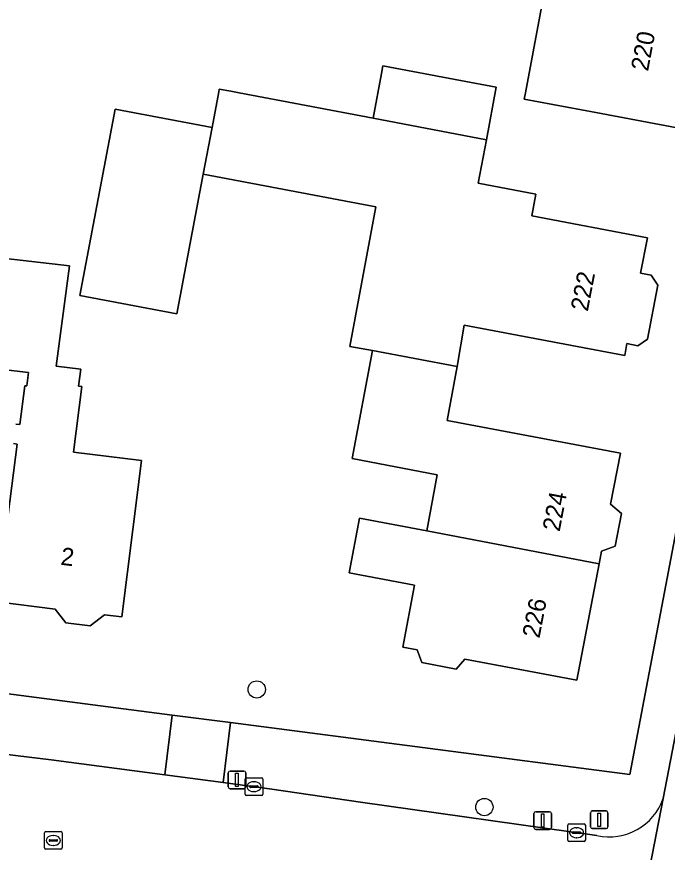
# Model space of a CAD drawing. Extents: x 161258 to 161838, y 380833 to 381727.
# Drawn here: x 161737.48 to 161774.37, y 381335.28 to 381382.67 of the extents above; entities that cross this region are included whole.
import ezdxf

# ---------------------------------------------------------------- set-up
doc = ezdxf.new("R2010")
doc.units = 0
for name, color, linetype in [('IMGEO_Boom', 7, 'Continuous'), ('IMGEO_Erf', 7, 'Continuous'), ('IMGEO_Fietspad_gesloten', 7, 'Continuous'), ('IMGEO_Kolk', 7, 'Continuous'), ('IMGEO_Lichtmast', 7, 'Continuous'), ('IMGEO_Pand', 7, 'Continuous'), ('IMGEO_Pand_nummerreeks', 7, 'Continuous'), ('IMGEO_Rijbaan_lokaal_open', 7, 'Continuous'), ('IMGEO_Rioolput', 7, 'Continuous'), ('IMGEO_Verkeersregelinstallatiepaal', 7, 'Continuous'), ('IMGEO_Voetpad_open', 7, 'Continuous')]:
    doc.layers.add(name, color=color, linetype=linetype)

msp = doc.modelspace()

# ---------------------------------------------------------------- linework, layer by layer
at = {"layer": 'IMGEO_Boom'}
for centre in [(161751.09, 381344.514), (161764, 381337.844)]:
    msp.add_circle(centre, 0.489, dxfattribs=at)
at = {"layer": 'IMGEO_Erf'}
for points in [[(161712.163, 381347.496), (161746.295, 381343.062), (161749.605, 381342.632), (161772.254, 381339.69), (161786.798, 381416.269), (161787.036, 381416.236), (161788.344, 381422.794), (161783.743, 381423.687), (161780.505, 381424.315), (161777.422, 381424.913), (161778.75, 381431.76), (161775.848, 381432.311), (161776.306, 381434.768), (161782.251, 381433.662), (161783.039, 381437.877), (161784.344, 381444.861), (161780.238, 381445.628), (161780.029, 381444.508), (161772.824, 381445.856)], [(161735.68, 381369.079), (161740.464, 381368.537), (161739.721, 381362.851), (161741.107, 381362.678), (161740.985, 381361.71), (161741.162, 381361.688), (161740.696, 381357.98), (161744.554, 381357.496), (161744.065, 381353.595), (161743.442, 381348.633), (161742.465, 381348.756), (161741.649, 381348.122), (161740.257, 381348.296), (161739.661, 381349.064), (161736.377, 381349.475)], [(161737.432, 381359.565), (161737.662, 381359.537), (161737.938, 381361.743), (161738.052, 381361.73), (161738.149, 381362.494), (161735.049, 381362.846)], [(161737, 381354.437), (161737.501, 381358.434), (161737.293, 381358.46)]]:
    msp.add_lwpolyline(points, dxfattribs=at)
for points in [[(161772.844, 381389.277), (161772.118, 381385.422), (161776.791, 381384.539), (161775.234, 381376.303), (161770.322, 381377.232), (161766.263, 381377.999), (161766.33, 381378.356), (161767.586, 381385.049), (161767.219, 381385.119), (161765.849, 381385.38), (161763.911, 381385.748), (161763.533, 381385.82), (161763.122, 381385.898), (161764.068, 381390.901), (161758.838, 381391.869), (161759.471, 381395.29), (161765.709, 381394.135), (161765.076, 381390.715), (161766.095, 381390.526)], [(161757.685, 381376.912), (161758.164, 381379.441), (161758.247, 381379.879), (161762.644, 381379.05), (161764.673, 381378.668), (161764.111, 381375.692), (161763.646, 381373.225), (161766.918, 381372.607), (161766.684, 381371.367), (161773.243, 381370.131), (161772.855, 381368.115), (161773.458, 381368.002), (161773.832, 381367.453), (161773.254, 381364.387), (161772.706, 381364.012), (161772.086, 381364.128), (161771.956, 381363.458), (161762.847, 381365.174), (161762.463, 381362.825), (161761.888, 381359.773), (161771.713, 381357.922), (161771.157, 381355.03), (161771.772, 381354.502), (161771.42, 381352.634), (161770.644, 381352.361), (161770.505, 381351.637), (161769.237, 381345.041), (161762.882, 381346.239), (161762.394, 381345.671), (161760.449, 381346.038), (161760.196, 381346.759), (161759.381, 381346.913), (161760.044, 381350.429), (161756.34, 381351.127), (161756.923, 381354.222), (161760.728, 381353.505), (161761.329, 381356.694), (161756.496, 381357.605), (161757.651, 381363.731), (161756.374, 381363.971), (161757.841, 381371.885), (161748.057, 381373.742), (161746.562, 381365.815), (161741.062, 381366.849), (161743.058, 381377.43), (161748.556, 381376.386), (161748.939, 381378.417), (161748.967, 381378.567), (161749.615, 381378.444), (161750.102, 381378.351)]]:
    msp.add_lwpolyline(points, close=True, dxfattribs=at)
at = {"layer": 'IMGEO_Fietspad_gesloten'}
msp.add_lwpolyline([(161776.826, 381341.153), (161777.049, 381342.372), (161777.831, 381346.224), (161778.926, 381351.995), (161776.847, 381352.346), (161774.147, 381338.339), (161771.375, 381324.109), (161770.217, 381317.745), (161772.289, 381317.394), (161772.887, 381320.696), (161773.43, 381323.525)], close=True, dxfattribs=at)
at = {"layer": 'IMGEO_Kolk'}
for p, q in [((161750.43, 381338.576), (161750.43, 381339.428)), ((161750.505, 381339.502), (161751.357, 381339.502)), ((161751.431, 381339.428), (161751.431, 381338.576)), ((161750.689, 381338.996), (161750.689, 381339.008)), ((161751.127, 381338.959), (161750.729, 381338.959)), ((161750.732, 381339.045), (161751.13, 381339.045)), ((161750.918, 381339.282), (161750.943, 381339.282)), ((161751.173, 381339.008), (161751.173, 381338.996)), ((161751.357, 381338.502), (161750.505, 381338.502)), ((161750.941, 381338.722), (161750.916, 381338.722)), ((161768.726, 381335.963), (161768.726, 381336.815)), ((161768.801, 381336.889), (161769.653, 381336.889)), ((161769.214, 381336.669), (161769.239, 381336.669)), ((161769.727, 381336.815), (161769.727, 381335.963)), ((161768.985, 381336.383), (161768.985, 381336.395)), ((161769.423, 381336.346), (161769.025, 381336.346)), ((161769.028, 381336.432), (161769.426, 381336.432)), ((161769.237, 381336.109), (161769.212, 381336.109)), ((161769.469, 381336.395), (161769.469, 381336.383)), ((161769.653, 381335.889), (161768.801, 381335.889))]:
    msp.add_line(p, q, dxfattribs=at)
for points in [[(161750.43, 381338.576), (161750.43, 381339.428)], [(161750.505, 381339.502), (161751.357, 381339.502)], [(161751.431, 381339.428), (161751.431, 381338.576)], [(161751.357, 381338.502), (161750.505, 381338.502)], [(161768.726, 381335.963), (161768.726, 381336.815)], [(161768.801, 381336.889), (161769.653, 381336.889)], [(161769.727, 381336.815), (161769.727, 381335.963)], [(161769.653, 381335.889), (161768.801, 381335.889)]]:
    msp.add_lwpolyline(points, dxfattribs=at)
for centre, radius, start, end in [((161750.507, 381339.426), 0.0765, 91.552, 178.448), ((161750.507, 381339.426), 0.0765, 91.552, 178.448), ((161751.355, 381339.426), 0.0765, 1.552, 88.448), ((161751.355, 381339.426), 0.0765, 1.552, 88.448), ((161750.729, 381339.005), 0.0403, 85.8775, 175.7526), ((161750.726, 381338.995), 0.0366, 178.938, 274.7102), ((161751.13, 381339.002), 0.043, 264.8664, 352.4533), ((161751.134, 381339.007), 0.0386, 1.7309, 96.639), ((161750.507, 381338.578), 0.0765, 181.552, 268.448), ((161750.507, 381338.578), 0.0765, 181.552, 268.448), ((161751.355, 381338.578), 0.0765, 271.552, 358.448), ((161751.355, 381338.578), 0.0765, 271.552, 358.448), ((161768.803, 381336.813), 0.0765, 91.552, 178.448), ((161768.803, 381336.813), 0.0765, 91.552, 178.448), ((161769.651, 381336.813), 0.0765, 1.552, 88.448), ((161769.651, 381336.813), 0.0765, 1.552, 88.448), ((161769.025, 381336.392), 0.0403, 85.8775, 175.7526), ((161769.022, 381336.382), 0.0366, 178.938, 274.7102), ((161769.426, 381336.389), 0.043, 264.8664, 352.4533), ((161769.43, 381336.394), 0.0386, 1.7309, 96.639), ((161768.803, 381335.965), 0.0765, 181.552, 268.448), ((161768.803, 381335.965), 0.0765, 181.552, 268.448), ((161769.651, 381335.965), 0.0765, 271.552, 358.448), ((161769.651, 381335.965), 0.0765, 271.552, 358.448)]:
    msp.add_arc(centre, radius, start, end, dxfattribs=at)
for centre, major_axis, ratio, start_param, end_param in [((161750.917, 381339.002), (-0.387, 0.002), 0.722429, 4.712389, 7.853982), ((161750.942, 381339.002), (-0.39, 0.002), 0.717154, 1.570796, 4.712389), ((161769.213, 381336.389), (-0.387, 0.002), 0.722429, 4.712389, 7.853982), ((161769.238, 381336.389), (-0.39, 0.002), 0.717154, 1.570796, 4.712389)]:
    msp.add_ellipse(centre, major_axis=major_axis, ratio=ratio, start_param=start_param, end_param=end_param, dxfattribs=at)
at = {"layer": 'IMGEO_Lichtmast'}
for p, q in [((161749.574, 381339.885), (161750.364, 381339.885)), ((161750.364, 381339.885), (161749.574, 381339.885)), ((161749.474, 381338.985), (161749.474, 381339.785)), ((161749.474, 381339.785), (161749.474, 381338.985)), ((161750.464, 381339.785), (161750.464, 381338.985)), ((161750.464, 381338.985), (161750.464, 381339.785)), ((161750.364, 381338.885), (161749.574, 381338.885)), ((161749.574, 381338.885), (161750.364, 381338.885)), ((161766.811, 381336.679), (161766.811, 381337.479)), ((161766.811, 381337.479), (161766.811, 381336.679)), ((161766.911, 381337.579), (161767.701, 381337.579)), ((161767.701, 381337.579), (161766.911, 381337.579)), ((161767.801, 381337.479), (161767.801, 381336.679)), ((161767.801, 381336.679), (161767.801, 381337.479)), ((161767.701, 381336.579), (161766.911, 381336.579)), ((161766.911, 381336.579), (161767.701, 381336.579))]:
    msp.add_line(p, q, dxfattribs=at)
for points in [[(161749.894, 381339.76), (161750.044, 381339.76), (161750.044, 381339.01), (161749.894, 381339.01), (161749.894, 381339.76)], [(161767.231, 381337.454), (161767.381, 381337.454), (161767.381, 381336.704), (161767.231, 381336.704), (161767.231, 381337.454)]]:
    msp.add_lwpolyline(points, dxfattribs=at)
for centre, start, end in [((161749.574, 381339.785), 90, 180), ((161749.574, 381339.785), 90, 180), ((161750.364, 381339.785), 0, 90), ((161750.364, 381339.785), 360, 90), ((161749.574, 381338.985), 180, 270), ((161749.574, 381338.985), 180, 270), ((161750.364, 381338.985), 270, 0), ((161750.364, 381338.985), 270, 0), ((161766.911, 381337.479), 90, 180), ((161766.911, 381337.479), 90, 180), ((161767.701, 381337.479), 0, 90), ((161767.701, 381337.479), 360, 90), ((161766.911, 381336.679), 180, 270), ((161766.911, 381336.679), 180, 270), ((161767.701, 381336.679), 270, 0), ((161767.701, 381336.679), 270, 0)]:
    msp.add_arc(centre, 0.1, start, end, dxfattribs=at)
at = {"layer": 'IMGEO_Pand'}
for points in [[(161772.844, 381389.277), (161766.095, 381390.526), (161765.076, 381390.715), (161764.068, 381390.901), (161763.122, 381385.898), (161763.533, 381385.82), (161763.911, 381385.748), (161765.849, 381385.38), (161767.219, 381385.119), (161767.586, 381385.049), (161766.33, 381378.356), (161766.263, 381377.999), (161770.322, 381377.232), (161775.234, 381376.303), (161776.791, 381384.539), (161772.118, 381385.422)], [(161764.673, 381378.668), (161762.644, 381379.05), (161758.247, 381379.879), (161758.164, 381379.441), (161757.685, 381376.912), (161764.111, 381375.692)], [(161766.684, 381371.367), (161766.918, 381372.607), (161763.646, 381373.225), (161764.111, 381375.692), (161757.685, 381376.912), (161750.102, 381378.351), (161749.615, 381378.444), (161748.967, 381378.567), (161748.939, 381378.417), (161748.556, 381376.386), (161748.057, 381373.742), (161757.841, 381371.885), (161756.374, 381363.971), (161757.651, 381363.731), (161762.463, 381362.825), (161762.847, 381365.174), (161771.956, 381363.458), (161772.086, 381364.128), (161772.706, 381364.012), (161773.254, 381364.387), (161773.832, 381367.453), (161773.458, 381368.002), (161772.855, 381368.115), (161773.243, 381370.131)], [(161748.057, 381373.742), (161748.556, 381376.386), (161743.058, 381377.43), (161741.062, 381366.849), (161746.562, 381365.815)], [(161770.505, 381351.637), (161770.644, 381352.361), (161771.42, 381352.634), (161771.772, 381354.502), (161771.157, 381355.03), (161771.713, 381357.922), (161761.888, 381359.773), (161762.463, 381362.825), (161757.651, 381363.731), (161756.496, 381357.605), (161761.329, 381356.694), (161760.728, 381353.505)], [(161770.505, 381351.637), (161760.728, 381353.505), (161756.923, 381354.222), (161756.34, 381351.127), (161760.044, 381350.429), (161759.381, 381346.913), (161760.196, 381346.759), (161760.449, 381346.038), (161762.394, 381345.671), (161762.882, 381346.239), (161769.237, 381345.041)]]:
    msp.add_lwpolyline(points, close=True, dxfattribs=at)
for points in [[(161736.377, 381349.475), (161739.661, 381349.064), (161740.257, 381348.296), (161741.649, 381348.122), (161742.465, 381348.756), (161743.442, 381348.633), (161744.065, 381353.595), (161744.554, 381357.496), (161740.696, 381357.98), (161741.162, 381361.688), (161740.985, 381361.71), (161741.107, 381362.678), (161739.721, 381362.851), (161740.464, 381368.537), (161735.68, 381369.079)], [(161735.049, 381362.846), (161738.149, 381362.494), (161738.052, 381361.73), (161737.938, 381361.743), (161737.662, 381359.537), (161737.432, 381359.565)], [(161737.293, 381358.46), (161737.501, 381358.434), (161737, 381354.437)]]:
    msp.add_lwpolyline(points, dxfattribs=at)
at = {"layer": 'IMGEO_Rijbaan_lokaal_open'}
for points in [[(161756.972, 381338.129), (161751.938, 381338.869), (161749.179, 381339.233), (161745.88, 381339.669), (161739.43, 381340.521), (161735.362, 381341.02), (161729.822, 381341.699), (161727.547, 381341.978), (161717.901, 381343.221), (161711.839, 381343.942), (161711.557, 381343.975), (161710.75, 381344.069)], [(161770.386, 381336.224), (161756.972, 381338.129)], [(161771.375, 381324.109), (161774.147, 381338.339)]]:
    msp.add_lwpolyline(points, dxfattribs=at)
msp.add_arc((161771.067, 381339.415), 3.263, 257.9567, 340.7457, dxfattribs=at)
at = {"layer": 'IMGEO_Rioolput'}
for p, q in [((161739.053, 381335.525), (161739.053, 381336.377)), ((161739.128, 381336.451), (161739.98, 381336.451)), ((161739.541, 381336.231), (161739.566, 381336.231)), ((161740.054, 381336.377), (161740.054, 381335.525)), ((161739.312, 381335.945), (161739.312, 381335.957)), ((161739.75, 381335.908), (161739.352, 381335.908)), ((161739.355, 381335.994), (161739.753, 381335.994)), ((161739.564, 381335.671), (161739.539, 381335.671)), ((161739.796, 381335.957), (161739.796, 381335.945)), ((161739.98, 381335.451), (161739.128, 381335.451))]:
    msp.add_line(p, q, dxfattribs=at)
for points in [[(161739.053, 381335.525), (161739.053, 381336.377)], [(161739.128, 381336.451), (161739.98, 381336.451)], [(161740.054, 381336.377), (161740.054, 381335.525)], [(161739.98, 381335.451), (161739.128, 381335.451)]]:
    msp.add_lwpolyline(points, dxfattribs=at)
for centre, radius, start, end in [((161739.13, 381336.375), 0.0765, 91.552, 178.448), ((161739.13, 381336.375), 0.0765, 91.552, 178.448), ((161739.978, 381336.375), 0.0765, 1.552, 88.448), ((161739.978, 381336.375), 0.0765, 1.552, 88.448), ((161739.352, 381335.954), 0.0403, 85.8775, 175.7526), ((161739.349, 381335.944), 0.0366, 178.938, 274.7102), ((161739.753, 381335.951), 0.043, 264.8664, 352.4533), ((161739.757, 381335.956), 0.0386, 1.7309, 96.639), ((161739.13, 381335.527), 0.0765, 181.552, 268.448), ((161739.13, 381335.527), 0.0765, 181.552, 268.448), ((161739.978, 381335.527), 0.0765, 271.552, 358.448), ((161739.978, 381335.527), 0.0765, 271.552, 358.448)]:
    msp.add_arc(centre, radius, start, end, dxfattribs=at)
for centre, major_axis, ratio, start_param, end_param in [((161739.54, 381335.951), (-0.387, 0.002), 0.722429, 4.712389, 7.853982), ((161739.565, 381335.951), (-0.39, 0.002), 0.717154, 1.570796, 4.712389)]:
    msp.add_ellipse(centre, major_axis=major_axis, ratio=ratio, start_param=start_param, end_param=end_param, dxfattribs=at)
at = {"layer": 'IMGEO_Verkeersregelinstallatiepaal'}
for p, q in [((161770.02, 381336.722), (161770.02, 381337.522)), ((161770.02, 381337.522), (161770.02, 381336.722)), ((161770.12, 381337.622), (161770.91, 381337.622)), ((161770.91, 381337.622), (161770.12, 381337.622)), ((161771.01, 381337.522), (161771.01, 381336.722)), ((161771.01, 381336.722), (161771.01, 381337.522)), ((161770.91, 381336.622), (161770.12, 381336.622)), ((161770.12, 381336.622), (161770.91, 381336.622))]:
    msp.add_line(p, q, dxfattribs=at)
msp.add_lwpolyline([(161770.44, 381337.497), (161770.59, 381337.497), (161770.59, 381336.747), (161770.44, 381336.747), (161770.44, 381337.497)], dxfattribs=at)
for centre, start, end in [((161770.12, 381337.522), 90, 180), ((161770.12, 381337.522), 90, 180), ((161770.91, 381337.522), 0, 90), ((161770.91, 381337.522), 360, 90), ((161770.12, 381336.722), 180, 270), ((161770.12, 381336.722), 180, 270), ((161770.91, 381336.722), 270, 0), ((161770.91, 381336.722), 270, 0)]:
    msp.add_arc(centre, 0.1, start, end, dxfattribs=at)
at = {"layer": 'IMGEO_Voetpad_open'}
for points in [[(161774.147, 381338.339), (161776.847, 381352.346), (161788.338, 381413.247), (161792.085, 381430.647), (161795.911, 381451.079), (161805.168, 381500), (161809.91, 381525.057)], [(161804.264, 381506.66), (161803.022, 381500), (161802.977, 381499.759), (161801.672, 381492.76), (161800.413, 381486.006), (161799.06, 381478.747), (161797.827, 381472.131), (161796.574, 381465.41), (161796.482, 381464.918), (161796.391, 381464.426), (161795.043, 381457.163), (161793.753, 381450.216), (161792.476, 381443.339), (161791.179, 381436.353), (161789.916, 381429.55), (161788.651, 381422.734), (161788.344, 381422.794), (161787.036, 381416.236), (161786.798, 381416.269), (161772.254, 381339.69), (161749.605, 381342.632)], [(161710.75, 381344.069), (161711.557, 381343.975), (161711.839, 381343.942), (161717.901, 381343.221), (161727.547, 381341.978), (161729.822, 381341.699), (161735.362, 381341.02), (161739.43, 381340.521), (161745.88, 381339.669), (161746.295, 381343.062), (161712.163, 381347.496), (161712.463, 381350.189), (161708.039, 381350.79), (161704.663, 381351.215)], [(161749.605, 381342.632), (161749.179, 381339.233), (161751.938, 381338.869), (161756.972, 381338.129), (161770.386, 381336.224)]]:
    msp.add_lwpolyline(points, dxfattribs=at)
msp.add_lwpolyline([(161749.605, 381342.632), (161746.295, 381343.062), (161745.88, 381339.669), (161749.179, 381339.233)], close=True, dxfattribs=at)
msp.add_arc((161771.067, 381339.415), 3.263, 257.9567, 340.7457, dxfattribs=at)

# ---------------------------------------------------------------- texts
at = {"layer": 'IMGEO_Pand_nummerreeks'}
for s, rotation, p in [('220', 79.2974, (161773.281, 381379.538)), ('222', 79.0854, (161769.863, 381365.915)), ('224', 79.1013, (161768.266, 381353.427)), ('2', 353.2036, (161739.933, 381351.59)), ('226', 79.1193, (161767.121, 381347.383))]:
    msp.add_text(s, height=1, rotation=rotation, dxfattribs=at).set_placement(p)

doc.saveas('drawing.dxf')
